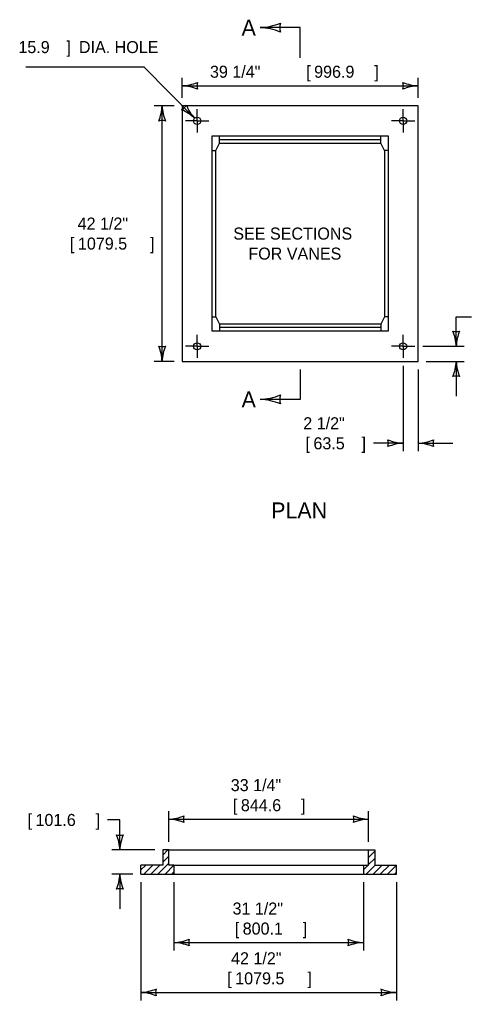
# Model space of a CAD drawing. Extents: x 49991.4 to 50041.6, y 49987.6 to 50011.4.
# Drawn here: x 50030.483 to 50032.737, y 49993.358 to 49998.251 of the extents above; entities that cross this region are included whole.
import ezdxf

# ---------------------------------------------------------------- set-up
doc = ezdxf.new("R2010")
doc.units = 0
for name, color, linetype in [('Level 1', 7, 'Continuous'), ('Level 2', 7, 'Continuous'), ('Level 3', 7, 'Continuous'), ('Level 5', 7, 'Continuous'), ('Level 6', 7, 'Continuous')]:
    doc.layers.add(name, color=color, linetype=linetype)

msp = doc.modelspace()

# ---------------------------------------------------------------- linework, layer by layer
at = {"layer": 'Level 1'}
for p, q in [((50031.4799, 49997.635), (50031.4799, 49997.6712)), ((50032.2849, 49997.635), (50032.2849, 49997.6712)), ((50031.4799, 49996.7325), (50031.4799, 49996.6962)), ((50032.2849, 49996.7325), (50032.2849, 49996.6962)), ((50031.1966, 49994.0825), (50031.2223, 49994.1081)), ((50031.2266, 49994.1081), (50032.2241, 49994.1081)), ((50032.2241, 49994.1067), (50032.2256, 49994.1081)), ((50031.1966, 49994.0471), (50031.2266, 49994.0771)), ((50032.2241, 49994.0714), (50032.2541, 49994.1014)), ((50032.2241, 49994.036), (50032.2541, 49994.066)), ((50031.0879, 49993.9881), (50031.0879, 49994.0331)), ((50031.0879, 49994.0091), (50031.1119, 49994.0331)), ((50031.1023, 49993.9881), (50031.1473, 49994.0331)), ((50031.1376, 49993.9881), (50031.1826, 49994.0331)), ((50031.173, 49993.9881), (50031.2266, 49994.0418)), ((50031.2084, 49993.9881), (50031.2529, 49994.0327)), ((50031.2529, 49994.0331), (50032.1979, 49994.0331)), ((50031.2529, 49994.0331), (50031.2529, 49993.9881)), ((50032.1979, 49994.0331), (50032.1979, 49993.9881)), ((50032.1979, 49994.0098), (50032.2213, 49994.0331)), ((50032.2116, 49993.9881), (50032.2566, 49994.0331)), ((50032.247, 49993.9881), (50032.292, 49994.0331)), ((50032.2823, 49993.9881), (50032.3273, 49994.0331)), ((50032.3177, 49993.9881), (50032.3627, 49994.0331)), ((50032.3629, 49993.9881), (50032.3629, 49994.0331)), ((50031.0879, 49993.9881), (50032.3629, 49993.9881)), ((50031.2437, 49993.9881), (50031.2529, 49993.9973)), ((50032.353, 49993.9881), (50032.3629, 49993.998))]:
    msp.add_line(p, q, dxfattribs=at)
for points in [[(50031.2936, 49996.5462), (50032.4711, 49996.5462), (50032.4711, 49997.8212), (50031.2936, 49997.8212)], [(50031.4436, 49997.6712), (50032.3211, 49997.6712), (50032.3211, 49996.6962), (50031.4436, 49996.6962)]]:
    msp.add_lwpolyline(points, close=True, dxfattribs=at)
for points in [[(50031.4436, 49997.599), (50031.4622, 49997.599), (50031.4799, 49997.635)], [(50031.4799, 49997.6527), (50032.2849, 49997.6527)], [(50031.4799, 49997.635), (50032.2849, 49997.635)], [(50032.3211, 49997.599), (50032.3026, 49997.599), (50032.2849, 49997.635)], [(50031.4622, 49996.7685), (50031.4622, 49997.599)], [(50032.3026, 49997.599), (50032.3026, 49996.7685)], [(50031.4436, 49996.7685), (50031.4622, 49996.7685), (50031.4799, 49996.7325)], [(50032.3211, 49996.7685), (50032.3026, 49996.7685), (50032.2849, 49996.7325)], [(50032.2849, 49996.7325), (50031.4799, 49996.7325)], [(50032.2849, 49996.7148), (50031.4799, 49996.7148)], [(50031.2529, 49994.0331), (50031.2266, 49994.0331), (50031.2266, 49994.1081), (50031.1966, 49994.1081), (50031.1966, 49994.0331), (50031.0879, 49994.0331)], [(50032.1979, 49994.0331), (50032.2241, 49994.0331), (50032.2241, 49994.1081), (50032.2541, 49994.1081), (50032.2541, 49994.0331), (50032.3629, 49994.0331)]]:
    msp.add_lwpolyline(points, dxfattribs=at)
for centre in [(50031.3686, 49997.7462), (50032.3961, 49997.7462), (50031.3686, 49996.6212), (50032.3961, 49996.6212)]:
    msp.add_circle(centre, 0.0178, dxfattribs=at)
at = {"layer": 'Level 3'}
for p, q in [((50031.1038, 49998.0142), (50030.5144, 49998.0142)), ((50031.3561, 49997.7589), (50031.1038, 49998.0142)), ((50031.2936, 49997.8612), (50031.2936, 49997.9612)), ((50032.4711, 49997.8612), (50032.4711, 49997.9612)), ((50031.2936, 49997.9212), (50032.4711, 49997.9212)), ((50031.2536, 49997.8212), (50031.1536, 49997.8212)), ((50031.1936, 49996.5462), (50031.1936, 49997.8212)), ((50032.6611, 49996.6212), (50032.6611, 49996.7689)), ((50032.6611, 49996.7689), (50032.7366, 49996.7689)), ((50032.494, 49996.6212), (50032.6611, 49996.6212)), ((50032.6611, 49996.6212), (50032.7011, 49996.6212)), ((50031.2536, 49996.5462), (50031.1536, 49996.5462)), ((50032.3961, 49996.5234), (50032.3961, 49996.2562)), ((50032.4711, 49996.5062), (50032.4711, 49996.2562)), ((50032.5111, 49996.5462), (50032.6611, 49996.5462)), ((50032.6611, 49996.5462), (50032.6611, 49996.3728)), ((50032.6611, 49996.5462), (50032.7011, 49996.5462)), ((50032.3961, 49996.2562), (50032.3961, 49996.0973)), ((50032.4711, 49996.2562), (50032.4711, 49996.0973)), ((50032.3961, 49996.1373), (50032.2485, 49996.1373)), ((50032.4711, 49996.1373), (50032.6445, 49996.1373)), ((50030.9829, 49994.2579), (50030.9219, 49994.2579)), ((50031.2266, 49994.1481), (50031.2266, 49994.3016)), ((50031.2266, 49994.2616), (50032.2241, 49994.2616)), ((50032.2241, 49994.1481), (50032.2241, 49994.3016)), ((50031.1566, 49994.1081), (50030.9429, 49994.1081)), ((50031.0479, 49993.9881), (50030.9429, 49993.9881)), ((50030.9829, 49993.9881), (50030.9829, 49993.8147)), ((50031.0879, 49993.9481), (50031.0879, 49993.3577)), ((50031.2529, 49993.9481), (50031.2529, 49993.606)), ((50032.1979, 49993.9481), (50032.1979, 49993.606)), ((50032.3629, 49993.9481), (50032.3629, 49993.3577)), ((50031.2529, 49993.646), (50032.1979, 49993.646)), ((50031.0879, 49993.3977), (50032.3629, 49993.3977))]:
    msp.add_line(p, q, dxfattribs=at)
msp.add_lwpolyline([(50030.9829, 49994.1081), (50030.9829, 49994.2579)], dxfattribs=at)
for centre, radius, start, end in [((50031.6671, 49998.5215), 0.3107, 272.8273, 292.0772), ((50031.6671, 49998.5215), 0.3107, 272.8273, 292.0772), ((50031.8533, 49998.2112), 0.073, 162.1388, 197.8612), ((50031.8533, 49998.2112), 0.073, 162.1388, 197.8612), ((50031.6702, 49997.9151), 0.2964, 67.456, 87.6395), ((50031.6702, 49997.9151), 0.2964, 67.456, 87.6395), ((50031.2822, 49998.154), 0.233, 272.8273, 292.0772), ((50031.2822, 49998.154), 0.233, 272.8273, 292.0772), ((50031.4219, 49997.9212), 0.0548, 162.1388, 197.8612), ((50031.4219, 49997.9212), 0.0548, 162.1388, 197.8612), ((50032.4803, 49998.1434), 0.2223, 247.456, 267.6395), ((50032.3429, 49997.9212), 0.0548, 342.1388, 17.8612), ((50032.4803, 49998.1434), 0.2223, 247.456, 267.6395), ((50032.3429, 49997.9212), 0.0548, 342.1388, 17.8612), ((50031.2845, 49997.6991), 0.2223, 67.456, 87.6395), ((50031.2845, 49997.6991), 0.2223, 67.456, 87.6395), ((50032.4826, 49997.6885), 0.233, 92.8273, 112.0772), ((50032.4826, 49997.6885), 0.233, 92.8273, 112.0772), ((50030.9715, 49997.8304), 0.2223, 337.456, 357.6395), ((50030.9715, 49997.8304), 0.2223, 337.456, 357.6395), ((50031.4264, 49997.8327), 0.233, 182.8273, 202.0772), ((50031.4264, 49997.8327), 0.233, 182.8273, 202.0772), ((50031.266, 49997.8501), 0.0548, 296.8076, 332.53), ((50031.1987, 49997.5872), 0.233, 47.4961, 66.746), ((50031.5205, 49997.9086), 0.2223, 202.1248, 222.3083), ((50031.1936, 49997.693), 0.0548, 72.1388, 107.8612), ((50031.1936, 49997.693), 0.0548, 72.1388, 107.8612), ((50032.6611, 49996.7495), 0.0548, 252.1388, 287.8612), ((50032.4284, 49996.6098), 0.233, 2.8273, 22.0772), ((50032.8833, 49996.6121), 0.2223, 157.456, 177.6395), ((50031.1936, 49996.6745), 0.0548, 252.1388, 287.8612), ((50030.9609, 49996.5348), 0.233, 2.8273, 22.0772), ((50031.4158, 49996.5371), 0.2223, 157.456, 177.6395), ((50032.439, 49996.5554), 0.2223, 337.456, 357.6395), ((50032.439, 49996.5554), 0.2223, 337.456, 357.6395), ((50032.8939, 49996.5577), 0.233, 182.8273, 202.0772), ((50032.8939, 49996.5577), 0.233, 182.8273, 202.0772), ((50032.6611, 49996.418), 0.0548, 72.1388, 107.8612), ((50032.6611, 49996.418), 0.0548, 72.1388, 107.8612), ((50031.6671, 49996.6665), 0.3107, 272.8273, 292.0772), ((50031.8533, 49996.3562), 0.073, 162.1388, 197.8612), ((50031.6702, 49996.0601), 0.2964, 67.456, 87.6395), ((50032.4053, 49996.3594), 0.2223, 247.456, 267.6395), ((50032.2679, 49996.1373), 0.0548, 342.1388, 17.8612), ((50032.4076, 49995.9046), 0.233, 92.8273, 112.0772), ((50032.4597, 49996.37), 0.233, 272.8273, 292.0772), ((50032.462, 49995.9152), 0.2223, 67.456, 87.6395), ((50032.5994, 49996.1373), 0.0548, 162.1388, 197.8612), ((50031.2151, 49994.4944), 0.233, 272.8273, 292.0772), ((50031.2151, 49994.4944), 0.233, 272.8273, 292.0772), ((50031.2175, 49994.0395), 0.2223, 67.456, 87.6395), ((50031.2175, 49994.0395), 0.2223, 67.456, 87.6395), ((50031.3548, 49994.2616), 0.0548, 162.1388, 197.8612), ((50031.3548, 49994.2616), 0.0548, 162.1388, 197.8612), ((50032.2333, 49994.4838), 0.2223, 247.456, 267.6395), ((50032.0959, 49994.2616), 0.0548, 342.1388, 17.8612), ((50032.2356, 49994.0289), 0.233, 92.8273, 112.0772), ((50030.9829, 49994.2364), 0.0548, 252.1388, 287.8612), ((50030.7502, 49994.0967), 0.233, 2.8273, 22.0772), ((50030.9829, 49994.2364), 0.0548, 252.1388, 287.8612), ((50030.7502, 49994.0967), 0.233, 2.8273, 22.0772), ((50031.2051, 49994.099), 0.2223, 157.456, 177.6395), ((50031.2051, 49994.099), 0.2223, 157.456, 177.6395), ((50030.7608, 49993.9973), 0.2223, 337.456, 357.6395), ((50031.2156, 49993.9996), 0.233, 182.8273, 202.0772), ((50030.9829, 49993.8599), 0.0548, 72.1388, 107.8612), ((50031.2414, 49993.8787), 0.233, 272.8273, 292.0772), ((50031.2414, 49993.8787), 0.233, 272.8273, 292.0772), ((50031.2437, 49993.4239), 0.2223, 67.456, 87.6395), ((50031.2437, 49993.4239), 0.2223, 67.456, 87.6395), ((50031.3811, 49993.646), 0.0548, 162.1388, 197.8612), ((50031.3811, 49993.646), 0.0548, 162.1388, 197.8612), ((50032.207, 49993.8681), 0.2223, 247.456, 267.6395), ((50032.0697, 49993.646), 0.0548, 342.1388, 17.8612), ((50032.207, 49993.8681), 0.2223, 247.456, 267.6395), ((50032.0697, 49993.646), 0.0548, 342.1388, 17.8612), ((50032.2094, 49993.4133), 0.233, 92.8273, 112.0772), ((50032.2094, 49993.4133), 0.233, 92.8273, 112.0772), ((50031.0764, 49993.6304), 0.233, 272.8273, 292.0772), ((50031.0787, 49993.1756), 0.2223, 67.456, 87.6395), ((50031.2161, 49993.3977), 0.0548, 162.1388, 197.8612), ((50032.372, 49993.6198), 0.2223, 247.456, 267.6395), ((50032.2347, 49993.3977), 0.0548, 342.1388, 17.8612), ((50032.3744, 49993.165), 0.233, 92.8273, 112.0772)]:
    msp.add_arc(centre, radius, start, end, dxfattribs=at)
at = {"layer": 'Level 5'}
for points in [[(50031.3686, 49997.7462), (50031.3686, 49997.7641), (50031.3686, 49997.8041)], [(50032.3961, 49997.7462), (50032.3961, 49997.7641), (50032.3961, 49997.8041)], [(50031.3686, 49997.7462), (50031.3508, 49997.7462), (50031.3108, 49997.7462)], [(50031.3686, 49997.7462), (50031.3865, 49997.7462), (50031.4265, 49997.7462)], [(50031.3686, 49997.7462), (50031.3686, 49997.7284), (50031.3686, 49997.6884)], [(50032.3961, 49997.7462), (50032.3783, 49997.7462), (50032.3383, 49997.7462)], [(50032.3961, 49997.7462), (50032.414, 49997.7462), (50032.454, 49997.7462)], [(50032.3961, 49997.7462), (50032.3961, 49997.7284), (50032.3961, 49997.6884)], [(50031.3686, 49996.6212), (50031.3686, 49996.6391), (50031.3686, 49996.6791)], [(50032.3961, 49996.6212), (50032.3961, 49996.6391), (50032.3961, 49996.6791)], [(50031.3686, 49996.6212), (50031.3508, 49996.6212), (50031.3108, 49996.6212)], [(50031.3686, 49996.6212), (50031.3865, 49996.6212), (50031.4265, 49996.6212)], [(50031.3686, 49996.6212), (50031.3686, 49996.6034), (50031.3686, 49996.5634)], [(50032.3961, 49996.6212), (50032.3783, 49996.6212), (50032.3383, 49996.6212)], [(50032.3961, 49996.6212), (50032.414, 49996.6212), (50032.454, 49996.6212)], [(50032.3961, 49996.6212), (50032.3961, 49996.6034), (50032.3961, 49996.5634)]]:
    msp.add_lwpolyline(points, dxfattribs=at)
at = {"layer": 'Level 6'}
for p, q in [((50031.8824, 49998.2112), (50031.6824, 49998.2112)), ((50031.8824, 49998.0612), (50031.8824, 49998.2112)), ((50031.8824, 49996.5062), (50031.8824, 49996.3562)), ((50031.8824, 49996.3562), (50031.6824, 49996.3562))]:
    msp.add_line(p, q, dxfattribs=at)

# ---------------------------------------------------------------- texts
at = {"layer": 'Level 2'}
for s, height, p in [('A', 0.08, (50031.5901, 49998.1712)), ('15.9', 0.06, (50030.4767, 49998.0842)), (']', 0.06, (50030.7167, 49998.0842)), (' DIA. HOLE', 0.06, (50030.7564, 49998.0842)), ('39 1/4" ', 0.06, (50031.4325, 49997.9612)), ('[', 0.06, (50031.9125, 49997.9612)), ('996.9', 0.06, (50031.9522, 49997.9612)), (']', 0.06, (50032.2522, 49997.9612)), ('42 1/2"', 0.06, (50030.7724, 49997.2037)), ('SEE SECTIONS', 0.06, (50031.549, 49997.1537)), ('[', 0.06, (50030.7341, 49997.1037)), ('1079.5', 0.06, (50030.7738, 49997.1037)), (']', 0.06, (50031.1338, 49997.1037)), ('FOR VANES', 0.06, (50031.624, 49997.0537)), ('A', 0.08, (50031.5901, 49996.3162)), ('2 1/2"', 0.06, (50031.8981, 49996.2073)), ('[', 0.06, (50031.9089, 49996.1073)), ('63.5', 0.06, (50031.9486, 49996.1073)), (']', 0.06, (50032.1886, 49996.1073)), ('PLAN', 0.08, (50031.7375, 49995.7621)), ('33 1/4"', 0.06, (50031.5362, 49994.4016)), ('[', 0.06, (50031.547, 49994.3016)), ('844.6', 0.06, (50031.5867, 49994.3016)), (']', 0.06, (50031.8867, 49994.3016)), ('[', 0.06, (50030.5224, 49994.2279)), ('101.6', 0.06, (50030.5621, 49994.2279)), (']', 0.06, (50030.8621, 49994.2279)), ('31 1/2"', 0.06, (50031.5451, 49993.786)), ('[', 0.06, (50031.556, 49993.686)), ('800.1', 0.06, (50031.5957, 49993.686)), (']', 0.06, (50031.8957, 49993.686)), ('42 1/2"', 0.06, (50031.5378, 49993.5377)), ('[', 0.06, (50031.5187, 49993.4377)), ('1079.5', 0.06, (50031.5584, 49993.4377)), (']', 0.06, (50031.9184, 49993.4377))]:
    msp.add_text(s, height=height, dxfattribs=at).set_placement(p)

doc.saveas('drawing.dxf')
